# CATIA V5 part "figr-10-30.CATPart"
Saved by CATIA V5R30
Part number: Part1
Bounding box of the stored display mesh (mm): x -72 to 28.909, y -84.823 to 54.826, z -29.324 to 42.024
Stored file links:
  D:\PROJECTS\CATIA V56R 2020\Resources\Parts File\c10_catia_v5_6r2020_prt\figr-10-30.CATPart
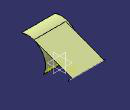
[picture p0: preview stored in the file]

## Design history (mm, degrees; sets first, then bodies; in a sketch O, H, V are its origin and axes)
Body1 (main body)
  Sketch1 on yz-plane, origin (0, 0, 0), H (0, 1, 0), V (0, 0, 1)
    arc A1 centre (-67.861, -7.2287) radius 49.2558 from (-84.8225, 39.0145) to (-23.8391, -29.3242) cw
  Extrude1: Element1 Sketch1, Lim1 20, Lim2 72
  Sketch2 on xy-plane, origin (0, 0, 0), H (1, 0, 0), V (0, 1, 0)
    line L1 (-67.3145, 54.8256) -> (28.9089, 54.8256)
    horizontal: L1 H
  Sweep1: type Segment, GuideCrv Sketch2, GuideSurf Extrude1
